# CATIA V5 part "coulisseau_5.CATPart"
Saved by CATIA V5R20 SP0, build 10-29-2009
Part number: sqlt_coulisseau_5
Publications: "Plan.1", "Point.1", "Plan.2", "Point.2", "Point.3", "Plan.3", "Droite.1", "Droite.2"
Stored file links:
  D:\ecole\thinkmotion\IAO\coulisseau_5.CATPart
  D:\ecole\thinkmotion\IAO\sqlt mecanisme coulisseau.CATProduct
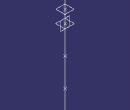
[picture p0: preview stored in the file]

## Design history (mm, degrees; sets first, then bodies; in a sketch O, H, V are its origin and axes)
External parameters (linked from other documents)
  External.largueur_rail_coulisseau = 50 mm
  `External.épaisseur_piece` = 20 mm
  External.largueur_rail_coulisseau.1 = 50 mm
Set1 "sqlt_coulisseau"
  Plane1: type Offset, RefPlane xy-plane, Offset 0
  Point1: (0, 0, 0)
  Plane2: type Offset, RefPlane zx-plane, Offset 0
  Point2: (30, 30 {= External.largueur_rail_coulisseau -20mm}, 0)
  Point3: (15, 15 {= (External.largueur_rail_coulisseau -20mm)/2}, 0)
  Plane3: type Offset, RefPlane Plane1, Offset 6.6667 {= `External.épaisseur_piece` /3}
  Line1: type PtDir, RefPoint Point3, Direction Plane1, Start 0, End 20
  Point4: type OnPlane, Support Plane3, H 0, V 0, Direction (1, 0, 0)
Body1 (main body)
